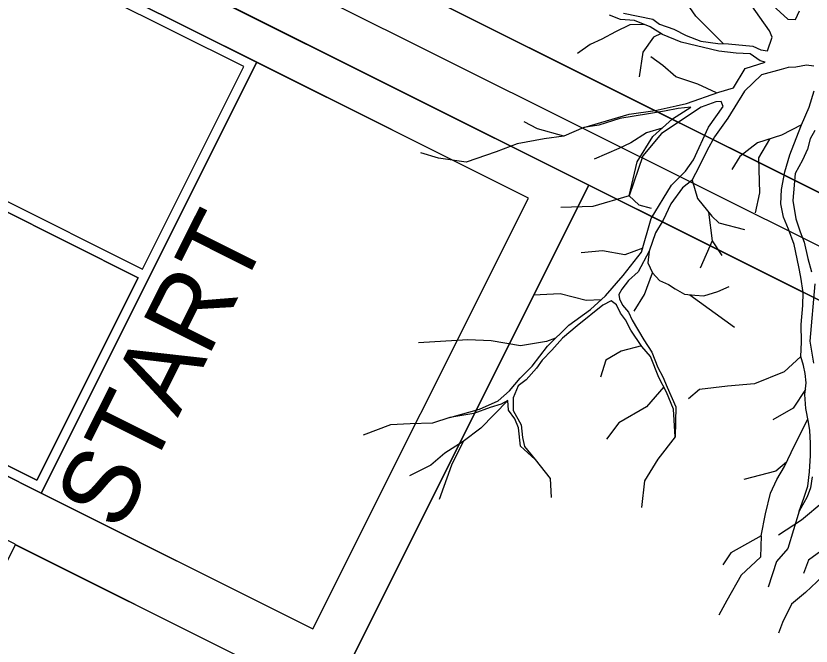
# Model space of a CAD drawing. Extents: x -504998 to -504814, y -1117353 to -1117234.
# Drawn here: x -504886.075 to -504881.95, y -1117290.935 to -1117287.663 of the extents above; entities that cross this region are included whole.
import ezdxf

# ---------------------------------------------------------------- set-up
doc = ezdxf.new("R2010")
doc.units = 0
for name, color, linetype in [('01_OPLOCENI', 7, 'Continuous'), ('01_ST tenká', 7, 'Continuous'), ('03_POPIS', 7, 'Continuous'), ('10_STROMY_NAVRH', 7, 'Continuous'), ('10_ZIVE_PLOTY_KVETOUCI', 7, 'Continuous'), ('_01_CYKLOSTEZKA', 7, 'Continuous'), ('_01_pl', 7, 'Continuous'), ('_01_reka', 7, 'Continuous'), ('_01_sport_plochy', 7, 'Continuous'), ('_01_ST tenká', 7, 'Continuous'), ('_02_pl_ cesta', 7, 'Continuous'), ('Default', 7, 'Continuous')]:
    doc.layers.add(name, color=color, linetype=linetype)

# ---------------------------------------------------------------- blocks, each defined once
blk = doc.blocks.new('stromm')
at = {"layer": 'Default'}
for p, q in [((-0.09282, 0.01526), (-0.10265, 0.02846)), ((-0.09282, 0.01526), (-0.07104, -0.00478)), ((-0.14307, 0.00628), (-0.15391, 0.00047)), ((-0.1319, 0.00709), (-0.14307, 0.00628)), ((-0.15391, 0.00047), (-0.16399, -0.00573)), ((-0.11879, 0.00088), (-0.12458, -0.00238)), ((-0.16399, -0.00573), (-0.1729, -0.00999)), ((-0.12458, -0.00238), (-0.13212, -0.01403)), ((-0.1729, -0.00999), (-0.1822, -0.01735)), ((-0.13212, -0.01403), (-0.13418, -0.03322)), ((-0.11635, -0.02362), (-0.12595, -0.01745)), ((-0.10607, -0.03184), (-0.11635, -0.02362)), ((-0.08894, -0.03664), (-0.10607, -0.03184)), ((-0.07454, -0.04281), (-0.08894, -0.03664)), ((-0.00824, -0.06434), (-0.02324, -0.07284)), ((-0.21026, -0.07639), (-0.22054, -0.07159)), ((-0.1149, -0.07164), (-0.12664, -0.0757)), ((-0.02324, -0.07284), (-0.04142, -0.0797)), ((-0.1897, -0.08118), (-0.21026, -0.07639)), ((-0.17472, -0.07388), (-0.1897, -0.08118)), ((-0.12664, -0.0757), (-0.13829, -0.08392)), ((-0.03233, -0.07627), (-0.03997, -0.09098)), ((-0.20478, -0.08392), (-0.22534, -0.08872)), ((-0.1897, -0.08118), (-0.20478, -0.08392)), ((-0.13829, -0.08392), (-0.1472, -0.08872)), ((-0.04142, -0.0797), (-0.05445, -0.09066)), ((-0.22534, -0.08872), (-0.24111, -0.09557)), ((-0.1472, -0.08872), (-0.16571, -0.09763)), ((-0.05445, -0.09066), (-0.05993, -0.10094)), ((-0.03997, -0.09098), (-0.03808, -0.11784)), ((-0.24111, -0.09557), (-0.26372, -0.10448)), ((-0.28497, -0.10242), (-0.29868, -0.099)), ((-0.26372, -0.10448), (-0.28497, -0.10242)), ((-0.09014, -0.11038), (-0.08529, -0.12438)), ((-0.03808, -0.11784), (-0.04073, -0.13334)), ((-0.13757, -0.12471), (-0.16502, -0.13395)), ((-0.13757, -0.12471), (-0.13006, -0.13121)), ((-0.08529, -0.12438), (-0.07364, -0.1374)), ((-0.16502, -0.13395), (-0.1897, -0.13601)), ((-0.13006, -0.13121), (-0.12047, -0.13326)), ((-0.07631, -0.13441), (-0.07272, -0.15613)), ((-0.07364, -0.1374), (-0.06815, -0.1422)), ((-0.06815, -0.1422), (-0.04838, -0.1464)), ((-0.07272, -0.15613), (-0.08084, -0.17762)), ((-0.07272, -0.15613), (-0.06461, -0.16708)), ((-0.12546, -0.16419), (-0.13899, -0.16982)), ((-0.15613, -0.16777), (-0.17257, -0.16982)), ((-0.13899, -0.16982), (-0.15613, -0.16777)), ((-0.12045, -0.16626), (-0.12098, -0.17524)), ((-0.12098, -0.17524), (-0.11728, -0.18264)), ((-0.12257, -0.19955), (-0.11728, -0.18264)), ((-0.11728, -0.18264), (-0.11147, -0.18845)), ((-0.11147, -0.18845), (-0.10459, -0.1911)), ((-0.10459, -0.1911), (-0.09931, -0.19427)), ((-0.09931, -0.19427), (-0.09191, -0.19797)), ((-0.07711, -0.19849), (-0.06654, -0.1948)), ((-0.06654, -0.1948), (-0.05808, -0.19057)), ((-0.12997, -0.21276), (-0.12257, -0.19955)), ((-0.09191, -0.19797), (-0.08398, -0.19849)), ((-0.08794, -0.19823), (-0.05241, -0.22145)), ((-0.08398, -0.19849), (-0.07711, -0.19849)), ((-0.18697, -0.20203), (-0.20753, -0.20409)), ((-0.16709, -0.20614), (-0.18697, -0.20203)), ((-0.15552, -0.20514), (-0.16709, -0.20614)), ((-0.18908, -0.2362), (-0.19588, -0.23904)), ((-0.2562, -0.24041), (-0.2939, -0.24452)), ((-0.23838, -0.24041), (-0.2562, -0.24041)), ((-0.21576, -0.24315), (-0.23838, -0.24041)), ((-0.19588, -0.23904), (-0.21576, -0.24315)), ((-0.12308, -0.23896), (-0.13831, -0.24383)), ((-0.00068, -0.24161), (-0.01296, -0.25389)), ((-0.13831, -0.24383), (-0.14996, -0.25137)), ((-0.14996, -0.25137), (-0.15339, -0.26439)), ((-0.01296, -0.25389), (-0.03525, -0.26417)), ((-0.05582, -0.26692), (-0.07706, -0.27034)), ((-0.03525, -0.26417), (-0.05582, -0.26692)), ((0.004, -0.2667), (-0.0048, -0.2816)), ((-0.10458, -0.26969), (-0.11706, -0.28564)), ((-0.07706, -0.27034), (-0.08529, -0.27788)), ((-0.22348, -0.28543), (-0.24318, -0.30756)), ((-0.11706, -0.28564), (-0.13762, -0.29865)), ((-0.0048, -0.2816), (-0.01988, -0.29119)), ((-0.00472, -0.31547), (0.0069, -0.2891)), ((-0.26725, -0.30058), (-0.28019, -0.30551)), ((-0.13762, -0.29865), (-0.14653, -0.31167)), ((-0.31241, -0.30825), (-0.33297, -0.31716)), ((-0.29733, -0.30688), (-0.31241, -0.30825)), ((-0.28019, -0.30551), (-0.29733, -0.30688)), ((-0.24318, -0.30756), (-0.2562, -0.31852)), ((-0.09402, -0.30757), (-0.10654, -0.32516)), ((-0.00942, -0.32642), (-0.00472, -0.31547)), ((-0.2562, -0.31852), (-0.26991, -0.32812)), ((-0.2562, -0.31852), (-0.26442, -0.33703)), ((-0.26991, -0.32812), (-0.28019, -0.33771)), ((-0.10654, -0.32516), (-0.11613, -0.3423)), ((-0.00793, -0.32294), (-0.01577, -0.33025)), ((-0.01474, -0.33675), (-0.00942, -0.32642)), ((-0.20059, -0.32986), (-0.18834, -0.34388)), ((-0.01577, -0.33025), (-0.04011, -0.33779)), ((-0.28019, -0.33771), (-0.29596, -0.34662)), ((-0.26442, -0.33703), (-0.27265, -0.36376)), ((-0.01913, -0.34738), (-0.01474, -0.33675)), ((-0.18834, -0.34388), (-0.18697, -0.35827)), ((-0.11613, -0.3423), (-0.1175, -0.36285)), ((-0.02226, -0.36334), (-0.01913, -0.34738)), ((0.02199, -0.35189), (0.00554, -0.36696)), ((-0.02476, -0.38024), (-0.02226, -0.36334)), ((0.00343, -0.36018), (-0.00412, -0.38918)), ((0.00554, -0.36696), (-0.01159, -0.3793)), ((-0.02476, -0.38024), (-0.04759, -0.39437)), ((-0.02476, -0.38024), (-0.02468, -0.39672)), ((-0.00412, -0.38918), (-0.01234, -0.39946)), ((0.02399, -0.38781), (0.01233, -0.39741)), ((-0.04759, -0.39437), (-0.05307, -0.40397)), ((-0.02468, -0.39672), (-0.03874, -0.41111)), ((-0.01234, -0.39946), (-0.01782, -0.41934)), ((0.01233, -0.39741), (0.00891, -0.40769)), ((-0.03874, -0.41111), (-0.04902, -0.43099)), ((0.02355, -0.40928), (0.01096, -0.42208)), ((0.01096, -0.42208), (0.00068, -0.43167)), ((-0.04902, -0.43099), (-0.05451, -0.44264)), ((0.00068, -0.43167), (-0.00549, -0.44606)), ((-0.00549, -0.44606), (-0.00823, -0.45429))]:
    blk.add_line(p, q, dxfattribs=at)
for points in [[(-0.01456, -0.02041), (-0.02037, -0.02094), (-0.02565, -0.02253), (-0.04064, -0.02728), (-0.05311, -0.04048), (-0.06495, -0.06163), (-0.07447, -0.07643), (-0.07975, -0.08753), (-0.08504, -0.09968), (-0.09032, -0.11078), (-0.09719, -0.11659), (-0.10565, -0.12927), (-0.11094, -0.14195), (-0.11622, -0.15199), (-0.12045, -0.16626), (-0.12825, -0.18252), (-0.13525, -0.18951), (-0.14001, -0.19638), (-0.14212, -0.20061), (-0.14159, -0.20378), (-0.13895, -0.20853), (-0.13419, -0.21382), (-0.13102, -0.21963), (-0.12151, -0.23443), (-0.11495, -0.24344), (-0.10988, -0.25504), (-0.10565, -0.26191), (-0.10195, -0.26983), (-0.09461, -0.28451), (-0.09402, -0.30757), (-0.09641, -0.28636), (-0.10223, -0.27365), (-0.10866, -0.26277), (-0.11575, -0.24681), (-0.1227, -0.23947), (-0.13164, -0.22739), (-0.13615, -0.21976), (-0.14033, -0.21468), (-0.14362, -0.2084), (-0.1478, -0.20572), (-0.15407, -0.2093), (-0.17294, -0.22598), (-0.18375, -0.23596), (-0.1915, -0.24538), (-0.19857, -0.25346), (-0.20261, -0.25986), (-0.21001, -0.26895), (-0.21608, -0.27399), (-0.21952, -0.2832), (-0.21909, -0.29287), (-0.21237, -0.30361), (-0.21103, -0.31337), (-0.20901, -0.3201), (-0.20059, -0.32986), (-0.21203, -0.3201), (-0.21439, -0.30596), (-0.21742, -0.29924), (-0.22247, -0.29284), (-0.22348, -0.28543), (-0.22853, -0.28846), (-0.23661, -0.29149), (-0.24906, -0.29668), (-0.26725, -0.30058), (-0.24469, -0.29318), (-0.23088, -0.28611), (-0.22247, -0.27803), (-0.21473, -0.26793), (-0.20597, -0.25851), (-0.19486, -0.24246), (-0.17935, -0.22566), (-0.16322, -0.21307), (-0.15245, -0.20197), (-0.13957, -0.18574), (-0.12618, -0.16732), (-0.12019, -0.14112), (-0.10559, -0.11494), (-0.09548, -0.10384), (-0.08972, -0.0947), (-0.07929, -0.06918), (-0.06889, -0.05302), (-0.07058, -0.04931), (-0.07461, -0.04965), (-0.08573, -0.05433), (-0.11504, -0.07565), (-0.12862, -0.09341), (-0.13757, -0.12471), (-0.13288, -0.09828), (-0.12174, -0.07826), (-0.10713, -0.06412), (-0.09358, -0.05464), (-0.10319, -0.05592), (-0.11355, -0.05868), (-0.12565, -0.0611), (-0.14751, -0.06582), (-0.16332, -0.07146), (-0.17472, -0.07388), (-0.1406, -0.06197), (-0.12081, -0.05834), (-0.10491, -0.05419), (-0.09713, -0.05193), (-0.07277, -0.0421), (-0.06158, -0.03822), (-0.05338, -0.0232), (-0.03821, -0.01756), (-0.04212, -0.01659), (-0.04996, -0.01169), (-0.06067, -0.01169), (-0.07412, -0.01081), (-0.10319, -0.00512), (-0.11786, 0.00008), (-0.12738, 0.00559), (-0.13982, 0.00973), (-0.15053, 0.01008), (-0.15906, 0.01303)], [(-0.1483, 0.01513), (-0.12565, 0.01146), (-0.12046, 0.008), (-0.1094, 0.00455), (-0.09973, 0.00006), (-0.08832, -0.00374), (-0.07519, -0.00478), (-0.0669, -0.00478), (-0.04823, -0.00582), (-0.04201, -0.00824), (-0.03678, -0.00876), (-0.03377, 0.00192), (-0.03607, 0.00655), (-0.05191, 0.02694)], [(-0.03458, 0.02625), (-0.02237, 0.01608), (-0.01649, 0.01608), (-0.01389, 0.023)], [(0.00201, -0.06815), (-0.00109, -0.07467), (-0.0028, -0.08257), (-0.00624, -0.09116), (-0.01148, -0.10164), (-0.01232, -0.12256), (-0.00933, -0.1365), (-0.00555, -0.14611), (-0.00212, -0.15401), (0.00132, -0.16637), (0.00441, -0.17634)], [(0.0075, -0.18561), (0.00564, -0.2295), (0.00922, -0.2464)], [(0.01218, -0.3333), (0.01124, -0.34175), (0.00904, -0.34895), (0.00343, -0.36018), (0.00654, -0.34989), (0.00904, -0.34081), (0.00998, -0.32955), (0.00998, -0.31703), (0.00967, -0.30764), (0.00873, -0.29794), (0.00752, -0.29157), (0.00498, -0.28136), (0.00372, -0.27072), (0.00435, -0.26164), (0.0031, -0.25444), (0.00153, -0.2485), (-0.00068, -0.24161), (-0.00066, -0.23066), (-0.0016, -0.21721), (-0.00097, -0.2025), (-0.00128, -0.19248), (-0.00347, -0.18091), (-0.00535, -0.17308), (-0.0098, -0.15622), (-0.01456, -0.1446), (-0.01879, -0.13561), (-0.02143, -0.12557), (-0.02143, -0.11448), (-0.01931, -0.10074), (-0.01614, -0.08753), (-0.01191, -0.07484), (-0.00822, -0.06427), (-0.00293, -0.05053), (0.00024, -0.03785)], [(-0.00082, -0.01883), (-0.00663, -0.0183), (-0.01456, -0.02041)], [(-0.01456, -0.02041), (-0.02037, -0.02094), (-0.02565, -0.02253), (-0.04064, -0.02728), (-0.05311, -0.04048), (-0.06495, -0.06163), (-0.07447, -0.07643), (-0.07975, -0.08753), (-0.08504, -0.09968), (-0.09032, -0.11078), (-0.09719, -0.11659), (-0.10565, -0.12927), (-0.11094, -0.14195), (-0.11622, -0.15199), (-0.12045, -0.16626), (-0.12825, -0.18252), (-0.13525, -0.18951), (-0.14001, -0.19638), (-0.14212, -0.20061), (-0.14159, -0.20378), (-0.13895, -0.20853), (-0.13419, -0.21382), (-0.13102, -0.21963), (-0.12151, -0.23443), (-0.11495, -0.24344), (-0.10988, -0.25504), (-0.10565, -0.26191), (-0.10195, -0.26983), (-0.09461, -0.28451), (-0.09402, -0.30757), (-0.09641, -0.28636), (-0.10223, -0.27365), (-0.10866, -0.26277), (-0.11575, -0.24681), (-0.1227, -0.23947), (-0.13164, -0.22739), (-0.13615, -0.21976), (-0.14033, -0.21468), (-0.14362, -0.2084), (-0.1478, -0.20572), (-0.15407, -0.2093), (-0.17294, -0.22598), (-0.18375, -0.23596), (-0.1915, -0.24538), (-0.19857, -0.25346), (-0.20261, -0.25986), (-0.21001, -0.26895), (-0.21608, -0.27399), (-0.21952, -0.2832), (-0.21909, -0.29287), (-0.21237, -0.30361), (-0.21103, -0.31337), (-0.20901, -0.3201), (-0.20059, -0.32986), (-0.21203, -0.3201), (-0.21439, -0.30596), (-0.21742, -0.29924), (-0.22247, -0.29284), (-0.22348, -0.28543), (-0.22853, -0.28846), (-0.23661, -0.29149), (-0.24906, -0.29668), (-0.26725, -0.30058), (-0.24469, -0.29318), (-0.23088, -0.28611), (-0.22247, -0.27803), (-0.21473, -0.26793), (-0.20597, -0.25851), (-0.19486, -0.24246), (-0.17935, -0.22566), (-0.16322, -0.21307), (-0.15245, -0.20197), (-0.13957, -0.18574), (-0.12618, -0.16732), (-0.12019, -0.14112), (-0.10559, -0.11494), (-0.09548, -0.10384), (-0.08972, -0.0947), (-0.07929, -0.06918), (-0.06889, -0.05302), (-0.07058, -0.04931), (-0.07461, -0.04965), (-0.08573, -0.05433), (-0.11504, -0.07565), (-0.12862, -0.09341), (-0.13757, -0.12471), (-0.13288, -0.09828), (-0.12174, -0.07826), (-0.10713, -0.06412), (-0.09358, -0.05464), (-0.10319, -0.05592), (-0.11355, -0.05868), (-0.12565, -0.0611), (-0.14751, -0.06582), (-0.16332, -0.07146), (-0.17472, -0.07388), (-0.1406, -0.06197), (-0.12081, -0.05834), (-0.10491, -0.05419), (-0.09713, -0.05193), (-0.07277, -0.0421), (-0.06158, -0.03822), (-0.05338, -0.0232), (-0.03821, -0.01756), (-0.04212, -0.01659), (-0.04996, -0.01169), (-0.06067, -0.01169), (-0.07412, -0.01081), (-0.10319, -0.00512), (-0.11786, 0.00008), (-0.12738, 0.00559), (-0.13982, 0.00973), (-0.15053, 0.01008), (-0.15906, 0.01303)], [(-0.1483, 0.01513), (-0.12565, 0.01146), (-0.12046, 0.008), (-0.1094, 0.00455), (-0.09973, 0.00006), (-0.08832, -0.00374), (-0.07519, -0.00478), (-0.0669, -0.00478), (-0.04823, -0.00582), (-0.04201, -0.00824), (-0.03678, -0.00876), (-0.03377, 0.00192), (-0.03607, 0.00655), (-0.05191, 0.02694)], [(-0.03458, 0.02625), (-0.02237, 0.01608), (-0.01649, 0.01608), (-0.01389, 0.023)], [(0.00201, -0.06815), (-0.00109, -0.07467), (-0.0028, -0.08257), (-0.00624, -0.09116), (-0.01148, -0.10164), (-0.01232, -0.12256), (-0.00933, -0.1365), (-0.00555, -0.14611), (-0.00212, -0.15401), (0.00132, -0.16637), (0.00441, -0.17634)], [(0.0075, -0.18561), (0.00564, -0.2295), (0.00922, -0.2464)], [(0.01218, -0.3333), (0.01124, -0.34175), (0.00904, -0.34895), (0.00343, -0.36018), (0.00654, -0.34989), (0.00904, -0.34081), (0.00998, -0.32955), (0.00998, -0.31703), (0.00967, -0.30764), (0.00873, -0.29794), (0.00752, -0.29157), (0.00498, -0.28136), (0.00372, -0.27072), (0.00435, -0.26164), (0.0031, -0.25444), (0.00153, -0.2485), (-0.00068, -0.24161), (-0.00066, -0.23066), (-0.0016, -0.21721), (-0.00097, -0.2025), (-0.00128, -0.19248), (-0.00347, -0.18091), (-0.00535, -0.17308), (-0.0098, -0.15622), (-0.01456, -0.1446), (-0.01879, -0.13561), (-0.02143, -0.12557), (-0.02143, -0.11448), (-0.01931, -0.10074), (-0.01614, -0.08753), (-0.01191, -0.07484), (-0.00822, -0.06427), (-0.00293, -0.05053), (0.00024, -0.03785)], [(-0.00082, -0.01883), (-0.00663, -0.0183), (-0.01456, -0.02041)]]:
    blk.add_lwpolyline(points, dxfattribs=at)

msp = doc.modelspace()

# ---------------------------------------------------------------- linework, layer by layer
at = {"layer": '01_OPLOCENI'}
msp.add_line((-504871.8107, -1117293.9072), (-504902.0368, -1117278.7976), dxfattribs=at)
at = {"layer": '01_ST tenká'}
for p, q in [((-504871.6989, -1117293.6836), (-504900.8421, -1117279.1153)), ((-504871.9225, -1117294.1308), (-504899.187, -1117280.5016))]:
    msp.add_line(p, q, dxfattribs=at)
for points in [[(-504885.5626, -1117293.4612), (-504876.6179, -1117297.9325), (-504874.1587, -1117293.013), (-504883.1034, -1117288.5416)], [(-504874.1587, -1117293.013), (-504876.6179, -1117297.9325), (-504885.5626, -1117293.4612), (-504883.1034, -1117288.5416)]]:
    msp.add_lwpolyline(points, close=True, dxfattribs=at)
for points in [[(-504884.6876, -1117272.2712), (-504882.0666, -1117273.7468), (-504872.8334, -1117278.5708), (-504857.2196, -1117285.8398), (-504840.0713, -1117292.1542), (-504829.9134, -1117296.0841), (-504826.1704, -1117297.542)], [(-504979.6759, -1117286.5773), (-504975.526, -1117291.0899), (-504971.9235, -1117295.0966), (-504967.6088, -1117300.6858), (-504961.0547, -1117303.8176), (-504949.5875, -1117307.4915), (-504933.661, -1117313.2954), (-504916.6755, -1117320.5202), (-504900.9454, -1117326.1361), (-504889.0344, -1117332.5046), (-504883.9295, -1117337.2987), (-504881.8594, -1117339.4193)], [(-504980.2573, -1117288.1541), (-504977.7654, -1117290.881), (-504976.7845, -1117291.9663), (-504974.8421, -1117294.1624), (-504973.8807, -1117295.2734), (-504972.4656, -1117296.9629), (-504971.7648, -1117297.8134), (-504971.0756, -1117298.6743), (-504970.6189, -1117299.2506), (-504970.3936, -1117299.5421), (-504969.8956, -1117300.1584), (-504969.6267, -1117300.4769), (-504969.1689, -1117300.9465), (-504969.0067, -1117301.101), (-504968.6782, -1117301.3916), (-504968.5102, -1117301.5296), (-504967.6568, -1117302.187), (-504966.932, -1117302.6088), (-504965.846, -1117303.1601), (-504965.4838, -1117303.3302), (-504964.7678, -1117303.6537), (-504964.4161, -1117303.8068), (-504963.3583, -1117304.2604), (-504962.6531, -1117304.5505), (-504959.1287, -1117305.95), (-504956.3149, -1117306.9083), (-504952.123, -1117308.3232), (-504950.7322, -1117308.7922), (-504947.9498, -1117309.7531), (-504943.7774, -1117311.2202), (-504939.6182, -1117312.7648), (-504934.1021, -1117314.8927), (-504931.361, -1117315.9961), (-504925.8767, -1117318.2306), (-504923.1345, -1117319.3592), (-504918.9994, -1117321.0177), (-504917.6158, -1117321.5649), (-504914.8453, -1117322.6388), (-504913.4603, -1117323.1669), (-504909.3156, -1117324.753), (-504906.5664, -1117325.8124), (-504902.5013, -1117327.5141), (-504901.156, -1117328.1), (-504898.491, -1117329.3273), (-504897.1728, -1117329.9675), (-504894.5959, -1117331.324), (-504893.3371, -1117332.0403), (-504890.9079, -1117333.5714), (-504889.7421, -1117334.3846), (-504887.004, -1117336.5327), (-504885.4683, -1117337.9368), (-504883.9722, -1117339.4193)]]:
    msp.add_open_spline(points, degree=3, dxfattribs=at)
at = {"layer": '10_ZIVE_PLOTY_KVETOUCI'}
msp.add_lwpolyline([(-504871.9225, -1117294.1308), (-504901.0657, -1117279.5625), (-504900.8421, -1117279.1153), (-504871.6989, -1117293.6836)], dxfattribs=at)
at = {"layer": '_01_CYKLOSTEZKA'}
for points in [[(-504978.9989, -1117285.0174), (-504976.6999, -1117287.4225), (-504974.6874, -1117289.528), (-504972.1371, -1117292.1333), (-504971.6253, -1117292.6531), (-504970.5973, -1117293.6893), (-504970.0831, -1117294.2066), (-504969.0503, -1117295.2082), (-504968.53, -1117295.6934), (-504967.4657, -1117296.6092), (-504966.9225, -1117297.0363), (-504964.0811, -1117299.0487), (-504961.455, -1117300.27), (-504956.072, -1117302.5306), (-504953.3471, -1117303.5539), (-504945.1194, -1117306.4812), (-504939.5627, -1117308.242), (-504928.5735, -1117312.3504), (-504923.1854, -1117314.6767), (-504915.1077, -1117318.0387), (-504912.4097, -1117319.1296), (-504907.0009, -1117321.3287), (-504904.293, -1117322.4382), (-504900.2393, -1117324.181), (-504898.887, -1117324.773), (-504896.196, -1117326.0169), (-504894.8596, -1117326.6693), (-504892.2382, -1117328.0761), (-504890.9532, -1117328.8305), (-504888.4692, -1117330.4834), (-504887.2789, -1117331.3831), (-504883.8401, -1117334.2168), (-504881.7113, -1117336.2882), (-504879.2472, -1117338.7048), (-504878.8825, -1117339.0625), (-504878.518, -1117339.4193)], [(-504979.4381, -1117286.0051), (-504976.7939, -1117288.7714), (-504973.0127, -1117292.7274), (-504966.7797, -1117298.8785), (-504954.231, -1117304.8063), (-504936.6126, -1117309.8995), (-504917.359, -1117318.3118), (-504902.2312, -1117324.2343), (-504889.1764, -1117330.3605), (-504883.0674, -1117336.3576), (-504879.947, -1117339.4193)]]:
    msp.add_open_spline(points, degree=3, dxfattribs=at)
at = {"layer": '_01_pl'}
for points in [[(-504948.1838, -1117256.0088), (-504883.1034, -1117288.5416), (-504884.4448, -1117291.225), (-504886.0794, -1117290.4079), (-504886.0783, -1117290.4057), (-504900.5273, -1117283.1828), (-504900.8848, -1117283.898), (-504903.7177, -1117282.4818), (-504910.4257, -1117279.1273), (-504909.9784, -1117278.2329), (-504912.6616, -1117276.8911), (-504913.1089, -1117277.7855), (-504939.8496, -1117264.4132)], [(-504949.3862, -1117258.4143), (-504884.5343, -1117290.8451), (-504883.4161, -1117288.6091), (-504948.2684, -1117256.1781)], [(-504871.6989, -1117293.6836), (-504901.7028, -1117278.685), (-504900.5305, -1117276.3398), (-504900.7527, -1117276.2288), (-504900.642, -1117276.0072), (-504900.866, -1117275.8926), (-504900.5935, -1117275.3475), (-504892.8767, -1117280.1658), (-504883.692, -1117285.6476), (-504873.4361, -1117291.5937), (-504869.8877, -1117293.9359), (-504869.1911, -1117294.5448), (-504868.6161, -1117295.1475), (-504868.1369, -1117295.7406), (-504867.7626, -1117296.2801)]]:
    msp.add_lwpolyline(points, dxfattribs=at)
for points in [[(-504885.5626, -1117293.4612), (-504883.1034, -1117288.5416), (-504874.1587, -1117293.013), (-504876.6179, -1117297.9325)], [(-504894.6758, -1117307.6074), (-504892.048, -1117302.3526), (-504892.0496, -1117302.3518), (-504890.1035, -1117298.4581), (-504886.0781, -1117290.4085), (-504884.892, -1117291.0015), (-504893.4899, -1117308.2012)]]:
    msp.add_lwpolyline(points, close=True, dxfattribs=at)
at = {"layer": '_01_reka'}
msp.add_open_spline([(-504920.8779, -1117243.0082), (-504915.1309, -1117248.6296), (-504906.9699, -1117255.6932), (-504892.9531, -1117267.8809), (-504877.154, -1117276.5594), (-504857.2196, -1117285.8398), (-504843.8446, -1117290.7648), (-504837.4167, -1117293.2072)], degree=3, dxfattribs=at)
at = {"layer": '_01_sport_plochy'}
for points in [[(-504884.8258, -1117287.9042), (-504885.9439, -1117290.1402), (-504948.552, -1117258.8314), (-504947.4338, -1117256.5954)], [(-504885.9663, -1117290.0731), (-504948.4849, -1117258.8091), (-504947.9593, -1117257.7582), (-504885.4408, -1117289.0222)], [(-504885.4408, -1117289.0222), (-504947.9593, -1117257.7582), (-504948.4849, -1117258.8091), (-504885.9663, -1117290.0731)], [(-504885.9439, -1117290.1402), (-504884.5343, -1117290.8451), (-504883.4161, -1117288.6091), (-504884.8258, -1117287.9042)]]:
    msp.add_lwpolyline(points, close=True, dxfattribs=at)
at = {"layer": '_01_ST tenká'}
for p, q in [((-504947.937, -1117257.7134), (-504885.4184, -1117288.9775)), ((-504947.9593, -1117257.7582), (-504885.4408, -1117289.0222))]:
    msp.add_line(p, q, dxfattribs=at)
for points in [[(-504951.6824, -1117257.266), (-504885.9439, -1117290.1402), (-504884.8258, -1117287.9042), (-504950.5642, -1117255.03)], [(-504885.9439, -1117290.1402), (-504884.5343, -1117290.8451), (-504883.4161, -1117288.6091), (-504884.8258, -1117287.9042)]]:
    msp.add_lwpolyline(points, close=True, dxfattribs=at)
for points in [[(-504885.4184, -1117288.9775), (-504884.8929, -1117287.9265), (-504947.4114, -1117256.6625)], [(-504948.4849, -1117258.8091), (-504885.9663, -1117290.0731), (-504885.4408, -1117289.0222)]]:
    msp.add_lwpolyline(points, dxfattribs=at)
at = {"layer": '_02_pl_ cesta'}
msp.add_open_spline([(-504879.6125, -1117338.3466), (-504881.7113, -1117336.2882), (-504883.8401, -1117334.2168), (-504887.2789, -1117331.3831), (-504888.4692, -1117330.4834), (-504890.9532, -1117328.8305), (-504892.2382, -1117328.0761), (-504894.8596, -1117326.6693), (-504896.196, -1117326.0169), (-504898.887, -1117324.773), (-504900.2393, -1117324.181), (-504904.293, -1117322.4382), (-504907.0009, -1117321.3287), (-504912.4097, -1117319.1296), (-504915.1077, -1117318.0387), (-504923.1854, -1117314.6767), (-504928.5735, -1117312.3504), (-504939.5627, -1117308.242), (-504945.1194, -1117306.4812), (-504953.3471, -1117303.5539), (-504956.072, -1117302.5306), (-504961.455, -1117300.27), (-504964.0811, -1117299.0487), (-504966.9225, -1117297.0363), (-504967.4657, -1117296.6092), (-504968.53, -1117295.6934), (-504969.0503, -1117295.2082), (-504970.0831, -1117294.2066), (-504970.5973, -1117293.6893), (-504971.6253, -1117292.6531), (-504972.1371, -1117292.1333), (-504974.6874, -1117289.528), (-504976.6999, -1117287.4225), (-504978.9989, -1117285.0174)], degree=3, dxfattribs=at)

# ---------------------------------------------------------------- block references
at = {"layer": '10_STROMY_NAVRH', "xscale": 6.772928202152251, "yscale": 6.7729274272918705, "rotation": -2.5987541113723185}
msp.add_blockref('stromm', (-504881.9235, -1117287.7965), dxfattribs=at)

# ---------------------------------------------------------------- texts
at = {"layer": '03_POPIS'}
msp.add_text('START', height=0.39097, rotation=63.3672, dxfattribs=at).set_placement((-504885.5351, -1117290.3491))

doc.saveas('drawing.dxf')
